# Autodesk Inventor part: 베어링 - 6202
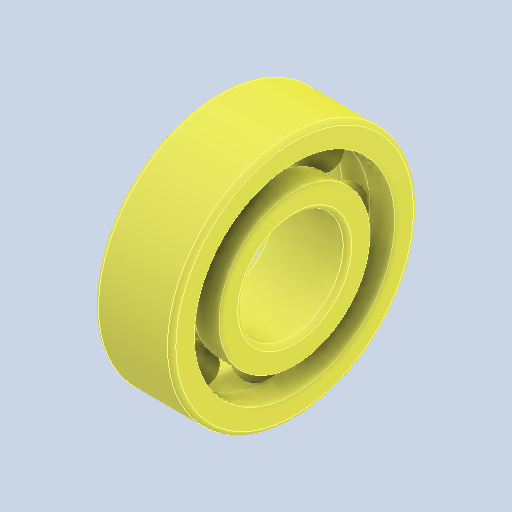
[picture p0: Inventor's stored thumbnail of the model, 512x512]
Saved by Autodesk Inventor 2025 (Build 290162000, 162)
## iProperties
Created: 2024-07
Part Number: 베어링 - 6202
Material: 강, 연강
Description: 깊은 그루브 볼 베어링
Document SubType Name: Modeling
Designer: myung
Density: 7.86 g/cm^3
Appearance: 기본값
Author: jhkim
Sending System: Autodesk Inventor 2025
Preprocessor: ST-DEVELOPER v20
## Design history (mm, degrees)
feature "Solid1"
feature "Solid1:1"
feature "Solid1:2"
feature "Solid1:3"
feature "Solid1:4"
feature "Solid1:5"
feature "Solid1:6"
feature "Solid1:7"
feature "Solid1:8"
feature "Solid1:9"
node "솔리드1"
node "솔리드2"
node "솔리드3"
node "솔리드4"
node "솔리드5"
node "솔리드6"
node "솔리드7"
node "솔리드8"
node "솔리드9"
node "솔리드10"
